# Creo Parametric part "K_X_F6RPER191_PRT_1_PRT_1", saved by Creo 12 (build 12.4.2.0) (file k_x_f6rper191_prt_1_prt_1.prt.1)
Units: Custom; MM, KILOGRAM, SECS

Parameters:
  PTC_WM_ITERATION = "0"
  PTC_WM_VERSION = "-.0"
  PTC_WM_LIFECYCLE_STATE = "In Work"
  PTC_WM_LIFECYCLE = "MO_CADDocument"
  PTC_WM_CREATED_BY = "Maximilian Roepper (Z0017RMS: MO)"
  PTC_WM_CREATED_ON = "18-Sep-26 11:36:42 AM"
  PTC_WM_MODIFIED_BY = "Maximilian Roepper (Z0017RMS: MO)"
  PTC_WM_MODIFIED_ON = "18-Sep-26 11:36:46 AM"
  PDMLINKNUMBER = "PDM000071455053"
  PTC_WM_NAME = "k_x_f6rper191_prt_1_prt_1.prt"
  PTC_WM_NUMBER = "PDM000071455053"

Other parameters: WEIGHT, WEIGHT_FACTOR, WEIGHT_ADD, _MASS_TEMP, _DIFF_TEMP, MC_ERRORS, SUPPLIER

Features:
  1. coordinate system
  2. datum plane "PRT_YZ"
  3. datum plane "PRT_XY"
  4. datum plane "PRT_XZ"
  5. coordinate system
  6. datum axis
  7. datum axis
  8. datum axis
  9. coordinate system
  10. imported feature
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
Other named items: PRT, SIEMENS_MO, DRW_VIEW_ORG, PRT_X, PRT_Y, PRT_Z, CS0, ROUGH_GROB

Layers: 00_STD_CSYS-KSYS, 01_STD_PLANES-EBENEN, 02_STD_AXES-ACHSEN, 03_STD_CSYS-KSYS, 24_IMPORT_FEAT-IMPORT_KE

Surfaces: 20 tabulated cylinder, 4 plane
